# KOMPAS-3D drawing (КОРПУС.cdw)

Referenced files in C:\WINDOWS\Temp\: kdruddqw.cd
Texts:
  КОРПУС
  Елена
  СК 1
  Жаренкова
  Подгорный
  НТИ МГУДТ
Dimensions and other numbers on the sheet: 80; 15; 30; 10; 25; 14; 40; 100; 60; 6; 70; 1:1; 1; 18.04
